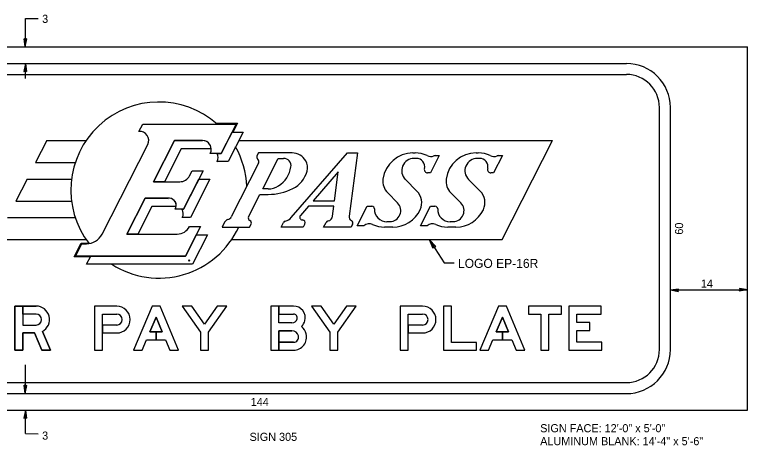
# Model space of a CAD drawing. Extents: x 60714 to 61340, y 9359 to 9750.
# Drawn here: x 60840.2 to 61093.4, y 9422.7 to 9571.4 of the extents above; entities that cross this region are included whole.
import ezdxf

# ---------------------------------------------------------------- set-up
doc = ezdxf.new("R2010")
doc.units = 0
for name, color, linetype in [('1', 7, 'Continuous'), ('2', 7, 'Continuous'), ('52', 7, 'Continuous'), ('GSBWFill', 7, 'Continuous'), ('SignPanel', 7, 'Continuous')]:
    doc.layers.add(name, color=color, linetype=linetype)

msp = doc.modelspace()

# ---------------------------------------------------------------- linework, layer by layer
at = {"layer": '1'}
for p, q in [((60843.93, 9570.16), (60848.33, 9570.13)), ((60843.93, 9560.27), (60843.93, 9570.16)), ((60843.93, 9549.38), (60843.93, 9554.57)), ((60983.43, 9493.77), (60988.67, 9485.78)), ((60988.67, 9485.78), (60992.11, 9485.78)), ((61066.77, 9476.35), (61093.37, 9476.35)), ((60843.93, 9440.57), (60843.93, 9450.46)), ((60843.93, 9426.76), (60843.93, 9434.87)), ((60843.93, 9426.76), (60848.33, 9426.73))]:
    msp.add_line(p, q, dxfattribs=at)
msp.add_circle((60900.51, 9486.52), 0.19, dxfattribs=at)
at = {"layer": '2'}
for p, q in [((60766.57, 9560.27), (61093.37, 9560.27)), ((61093.37, 9434.87), (61093.37, 9560.27)), ((60766.57, 9434.87), (61093.37, 9434.87))]:
    msp.add_line(p, q, dxfattribs=at)
at = {"layer": '52'}
for p, q in [((60843.91, 9560.35), (60843.47, 9563.13)), ((60843.96, 9562.91), (60843.47, 9563.13)), ((60843.91, 9560.35), (60843.73, 9563.01)), ((60843.91, 9560.35), (60844.45, 9563.11)), ((60843.91, 9560.35), (60844.19, 9563)), ((60844.45, 9563.11), (60843.96, 9562.91)), ((60843.93, 9554.57), (60843.39, 9551.81)), ((60843.93, 9554.57), (60843.65, 9551.92)), ((60843.93, 9554.57), (60844.37, 9551.8)), ((60843.93, 9554.57), (60844.11, 9551.91)), ((60843.39, 9551.81), (60843.88, 9552.02)), ((60843.88, 9552.02), (60844.37, 9551.8)), ((60983.43, 9493.77), (60984.68, 9490.74)), ((60985.7, 9491.41), (60983.43, 9493.77)), ((60984.68, 9490.74), (60985.06, 9491.28)), ((60985.06, 9491.28), (60985.7, 9491.41)), ((61066.77, 9476.35), (61069.55, 9476.8)), ((61066.77, 9476.35), (61069.43, 9476.54)), ((61066.77, 9476.35), (61069.53, 9475.82)), ((61066.77, 9476.35), (61069.42, 9476.08)), ((61069.33, 9476.31), (61069.55, 9476.8)), ((61069.53, 9475.82), (61069.33, 9476.31)), ((61090.81, 9476.4), (61090.59, 9475.91)), ((61093.37, 9476.35), (61090.59, 9475.91)), ((61093.37, 9476.35), (61090.61, 9476.89)), ((61090.61, 9476.89), (61090.81, 9476.4)), ((61093.37, 9476.35), (61090.71, 9476.63)), ((61093.37, 9476.35), (61090.71, 9476.17)), ((60843.91, 9440.65), (60843.47, 9443.43)), ((60843.96, 9443.21), (60843.47, 9443.43)), ((60843.91, 9440.65), (60843.73, 9443.31)), ((60843.91, 9440.65), (60844.45, 9443.41)), ((60843.91, 9440.65), (60844.19, 9443.3)), ((60844.45, 9443.41), (60843.96, 9443.21)), ((60843.93, 9434.87), (60843.39, 9432.11)), ((60843.93, 9434.87), (60843.65, 9432.22)), ((60843.93, 9434.87), (60844.37, 9432.1)), ((60843.93, 9434.87), (60844.11, 9432.21)), ((60843.39, 9432.11), (60843.88, 9432.32)), ((60843.88, 9432.32), (60844.37, 9432.1))]:
    msp.add_line(p, q, dxfattribs=at)
at = {"layer": 'GSBWFill'}
for p, q in [((60870.55, 9468.04), (60875.49, 9468.04)), ((60870.55, 9468.04), (60875.49, 9468.04)), ((60870.55, 9468.04), (60875.49, 9468.04)), ((60976.21, 9468.04), (60981.15, 9468.04)), ((60976.21, 9468.04), (60981.15, 9468.04)), ((60976.21, 9468.04), (60981.15, 9468.04)), ((60870.55, 9461.5), (60875.49, 9461.5)), ((60976.21, 9461.5), (60981.15, 9461.5)), ((60928.78, 9455.57), (60936.6, 9455.57))]:
    msp.add_line(p, q, dxfattribs=at)
for points in [[(60847.64, 9470.77), (60840.29, 9470.77), (60840.29, 9455.57), (60843.03, 9455.57), (60843.03, 9461.5), (60847.06, 9461.5), (60849.62, 9455.57), (60852.61, 9455.57), (60849.81, 9462.04)], [(60849.81, 9462.04), (60852.61, 9455.57), (60849.62, 9455.57), (60847.06, 9461.5), (60843.03, 9461.5), (60843.03, 9455.57), (60840.29, 9455.57), (60840.29, 9470.77), (60843.03, 9470.77), (60843.03, 9464.24), (60847.64, 9464.24)], [(60849.81, 9462.04), (60852.61, 9455.57), (60849.62, 9455.57), (60847.06, 9461.5), (60843.03, 9461.5), (60843.03, 9455.57), (60840.29, 9455.57), (60840.29, 9470.77), (60843.03, 9470.77), (60843.03, 9464.24), (60847.64, 9464.24)], [(60843.03, 9468.04), (60843.03, 9470.77), (60847.64, 9470.77)], [(60843.03, 9468.04), (60843.03, 9470.77), (60847.64, 9470.77)], [(60875.49, 9470.77), (60867.81, 9470.77), (60867.81, 9455.57), (60870.55, 9455.57), (60870.55, 9461.5)], [(60875.49, 9470.77), (60867.81, 9470.77), (60867.81, 9455.57), (60870.55, 9455.57), (60870.55, 9468.04)], [(60875.49, 9470.77), (60867.81, 9470.77), (60867.81, 9455.57), (60870.55, 9455.57), (60870.55, 9468.04)], [(60936.6, 9470.77), (60928.78, 9470.77), (60928.78, 9455.57)], [(60936.02, 9465), (60931.51, 9465), (60931.51, 9470.77), (60928.78, 9470.77), (60928.78, 9455.57), (60931.51, 9455.57)], [(60936.02, 9465), (60931.51, 9465), (60931.51, 9470.77), (60928.78, 9470.77), (60928.78, 9455.57), (60931.51, 9455.57)], [(60936.6, 9470.77), (60931.51, 9470.77), (60931.51, 9468.04), (60936.6, 9468.04)], [(60936.6, 9470.77), (60931.51, 9470.77), (60931.51, 9468.04), (60936.6, 9468.04)], [(60981.15, 9470.77), (60973.47, 9470.77), (60973.47, 9455.57), (60976.21, 9455.57), (60976.21, 9461.5)], [(60981.15, 9470.77), (60973.47, 9470.77), (60973.47, 9455.57), (60976.21, 9455.57), (60976.21, 9468.04)], [(60981.15, 9470.77), (60973.47, 9470.77), (60973.47, 9455.57), (60976.21, 9455.57), (60976.21, 9468.04)], [(60847.64, 9468.04), (60843.03, 9468.04), (60843.03, 9464.24), (60847.64, 9464.24)], [(60847.64, 9468.04), (60843.03, 9468.04)], [(60847.64, 9468.04), (60843.03, 9468.04)], [(60875.49, 9464.24), (60870.55, 9464.24), (60870.55, 9468.04)], [(60936.02, 9465), (60931.51, 9465), (60931.51, 9468.04), (60936.6, 9468.04)], [(60981.15, 9464.24), (60976.21, 9464.24), (60976.21, 9468.04)], [(60875.49, 9464.24), (60870.55, 9464.24), (60870.55, 9461.5), (60875.49, 9461.5)], [(60875.49, 9464.24), (60870.55, 9464.24), (60870.55, 9461.5), (60875.49, 9461.5)], [(60936.02, 9462.26), (60931.51, 9462.26), (60931.51, 9458.31), (60936.6, 9458.31)], [(60931.51, 9455.57), (60931.51, 9462.26), (60936.02, 9462.26)], [(60931.51, 9455.57), (60931.51, 9462.26), (60936.02, 9462.26)], [(60981.15, 9464.24), (60976.21, 9464.24), (60976.21, 9461.5), (60981.15, 9461.5)], [(60981.15, 9464.24), (60976.21, 9464.24), (60976.21, 9461.5), (60981.15, 9461.5)], [(60936.6, 9458.31), (60931.51, 9458.31), (60931.51, 9455.57), (60936.6, 9455.57)], [(60936.6, 9458.31), (60931.51, 9458.31), (60931.51, 9455.57), (60936.6, 9455.57)]]:
    msp.add_lwpolyline(points, dxfattribs=at)
for points in [[(60885.81, 9459.14), (60892.38, 9459.14), (60893.88, 9455.57), (60896.85, 9455.57), (60890.46, 9470.77), (60887.73, 9470.77), (60881.34, 9455.57), (60884.31, 9455.57)], [(60891.23, 9461.88), (60889.09, 9461.88), (60889.09, 9459.14), (60892.38, 9459.14), (60893.88, 9455.57), (60896.85, 9455.57), (60890.46, 9470.77), (60887.73, 9470.77), (60881.34, 9455.57), (60884.31, 9455.57), (60885.81, 9459.14), (60889.09, 9459.14), (60889.09, 9461.88), (60886.96, 9461.88), (60889.09, 9466.96)], [(60891.23, 9461.88), (60889.09, 9461.88), (60889.09, 9459.14), (60892.38, 9459.14), (60893.88, 9455.57), (60896.85, 9455.57), (60890.46, 9470.77), (60887.73, 9470.77), (60881.34, 9455.57), (60884.31, 9455.57), (60885.81, 9459.14), (60889.09, 9459.14), (60889.09, 9461.88), (60886.96, 9461.88), (60889.09, 9466.96)], [(60907.19, 9461.73), (60913.57, 9470.77), (60910.22, 9470.77), (60905.82, 9464.54), (60901.41, 9470.77), (60898.06, 9470.77), (60904.45, 9461.73), (60904.45, 9455.57), (60907.19, 9455.57)], [(60907.19, 9461.73), (60913.57, 9470.77), (60910.22, 9470.77), (60905.82, 9464.54), (60901.41, 9470.77), (60898.06, 9470.77), (60904.45, 9461.73), (60904.45, 9455.57), (60907.19, 9455.57)], [(60907.19, 9461.73), (60913.57, 9470.77), (60910.22, 9470.77), (60905.82, 9464.54), (60901.41, 9470.77), (60898.06, 9470.77), (60904.45, 9461.73), (60904.45, 9455.57), (60907.19, 9455.57)], [(60951.88, 9461.73), (60958.27, 9470.77), (60954.92, 9470.77), (60950.52, 9464.54), (60946.11, 9470.77), (60942.76, 9470.77), (60949.15, 9461.73), (60949.15, 9455.57), (60951.88, 9455.57)], [(60951.88, 9461.73), (60958.27, 9470.77), (60954.92, 9470.77), (60950.52, 9464.54), (60946.11, 9470.77), (60942.76, 9470.77), (60949.15, 9461.73), (60949.15, 9455.57), (60951.88, 9455.57)], [(60951.88, 9461.73), (60958.27, 9470.77), (60954.92, 9470.77), (60950.52, 9464.54), (60946.11, 9470.77), (60942.76, 9470.77), (60949.15, 9461.73), (60949.15, 9455.57), (60951.88, 9455.57)], [(60999.78, 9455.57), (60999.78, 9458.23), (60991.11, 9458.23), (60991.11, 9470.77), (60988.37, 9470.77), (60988.37, 9455.57)], [(60999.78, 9455.57), (60999.78, 9458.23), (60991.11, 9458.23), (60991.11, 9470.77), (60988.37, 9470.77), (60988.37, 9455.57)], [(60999.78, 9455.57), (60999.78, 9458.23), (60991.11, 9458.23), (60991.11, 9470.77), (60988.37, 9470.77), (60988.37, 9455.57)], [(61005.46, 9459.14), (61012.03, 9459.14), (61013.53, 9455.57), (61016.5, 9455.57), (61010.11, 9470.77), (61007.38, 9470.77), (61000.99, 9455.57), (61003.96, 9455.57)], [(61010.88, 9461.88), (61008.75, 9461.88), (61008.75, 9459.14), (61012.03, 9459.14), (61013.53, 9455.57), (61016.5, 9455.57), (61010.11, 9470.77), (61007.38, 9470.77), (61000.99, 9455.57), (61003.96, 9455.57), (61005.46, 9459.14), (61008.75, 9459.14), (61008.75, 9461.88), (61006.61, 9461.88), (61008.75, 9466.96)], [(61010.88, 9461.88), (61008.75, 9461.88), (61008.75, 9459.14), (61012.03, 9459.14), (61013.53, 9455.57), (61016.5, 9455.57), (61010.11, 9470.77), (61007.38, 9470.77), (61000.99, 9455.57), (61003.96, 9455.57), (61005.46, 9459.14), (61008.75, 9459.14), (61008.75, 9461.88), (61006.61, 9461.88), (61008.75, 9466.96)], [(61017.72, 9468.04), (61022.05, 9468.04), (61022.05, 9455.57), (61024.79, 9455.57), (61024.79, 9468.04), (61029.12, 9468.04), (61029.12, 9470.77), (61017.72, 9470.77)], [(61017.72, 9468.04), (61022.05, 9468.04), (61022.05, 9455.57), (61024.79, 9455.57), (61024.79, 9468.04), (61029.12, 9468.04), (61029.12, 9470.77), (61017.72, 9470.77)], [(61017.72, 9468.04), (61022.05, 9468.04), (61022.05, 9455.57), (61024.79, 9455.57), (61024.79, 9468.04), (61029.12, 9468.04), (61029.12, 9470.77), (61017.72, 9470.77)], [(61043.11, 9458.31), (61034.44, 9458.31), (61034.44, 9462.4), (61038.92, 9462.4), (61038.92, 9465.13), (61034.44, 9465.13), (61034.44, 9468.04), (61042.88, 9468.04), (61042.88, 9470.77), (61031.7, 9470.77), (61031.7, 9455.57), (61043.11, 9455.57)], [(61043.11, 9458.31), (61034.44, 9458.31), (61034.44, 9462.4), (61038.92, 9462.4), (61038.92, 9465.13), (61034.44, 9465.13), (61034.44, 9468.04), (61042.88, 9468.04), (61042.88, 9470.77), (61031.7, 9470.77), (61031.7, 9455.57), (61043.11, 9455.57)], [(61043.11, 9458.31), (61034.44, 9458.31), (61034.44, 9462.4), (61038.92, 9462.4), (61038.92, 9465.13), (61034.44, 9465.13), (61034.44, 9468.04), (61042.88, 9468.04), (61042.88, 9470.77), (61031.7, 9470.77), (61031.7, 9455.57), (61043.11, 9455.57)], [(60891.23, 9461.88), (60889.09, 9466.96), (60886.96, 9461.88)], [(61010.88, 9461.88), (61008.75, 9466.96), (61006.61, 9461.88)]]:
    msp.add_lwpolyline(points, close=True, dxfattribs=at)
for centre, radius, start, end in [((60847.64, 9466.14), 4.64, 297.837, 90), ((60847.64, 9466.14), 4.64, 297.837, 90), ((60847.64, 9466.14), 4.64, 297.837, 90), ((60936.6, 9466.75), 4.03, 345.5225, 90), ((60936.6, 9466.75), 4.03, 345.5225, 90), ((60936.6, 9466.75), 4.03, 345.5225, 90), ((60847.64, 9466.14), 1.9, 270, 90), ((60847.64, 9466.14), 1.9, 270, 90), ((60847.64, 9466.14), 1.9, 270, 90), ((60936.6, 9466.75), 1.29, 345.5225, 90), ((60936.6, 9466.75), 1.29, 345.5225, 90), ((60936.6, 9466.75), 1.29, 345.5225, 90), ((60936.02, 9466.9), 1.9, 270, 345.5225), ((60936.02, 9466.9), 1.9, 270, 345.5225), ((60936.02, 9466.9), 1.9, 270, 345.5225), ((60936.02, 9466.9), 4.64, 316.7114, 345.5225), ((60936.02, 9466.9), 4.64, 316.7114, 345.5225), ((60936.02, 9466.9), 4.64, 316.7114, 345.5225), ((60936.02, 9459.9), 2.36, 14.4775, 90), ((60936.02, 9459.9), 2.36, 14.4775, 90), ((60936.02, 9459.9), 2.36, 14.4775, 90), ((60936.02, 9459.9), 5.09, 14.4775, 48.4921), ((60936.02, 9459.9), 5.09, 14.4775, 48.4921), ((60936.02, 9459.9), 5.09, 14.4775, 48.4921), ((60936.6, 9460.06), 4.49, 270, 14.4775), ((60936.6, 9460.06), 4.49, 270, 14.4775), ((60936.6, 9460.06), 4.49, 270, 14.4775), ((60936.6, 9460.06), 1.75, 270, 14.4775), ((60936.6, 9460.06), 1.75, 270, 14.4775), ((60936.6, 9460.06), 1.75, 270, 14.4775)]:
    msp.add_arc(centre, radius, start, end, dxfattribs=at)
for centre, major_axis in [((60875.49, 9466.14), (0, 4.64)), ((60875.49, 9466.14), (0, 4.64)), ((60875.49, 9466.14), (0, 4.64)), ((60981.15, 9466.14), (0, 4.64)), ((60981.15, 9466.14), (0, 4.64)), ((60981.15, 9466.14), (0, 4.64)), ((60875.49, 9466.14), (0, 1.9)), ((60875.49, 9466.14), (0, 1.9)), ((60875.49, 9466.14), (0, 1.9)), ((60981.15, 9466.14), (0, 1.9)), ((60981.15, 9466.14), (0, 1.9)), ((60981.15, 9466.14), (0, 1.9))]:
    msp.add_ellipse(centre, major_axis=major_axis, ratio=0.999994, start_param=3.141593, end_param=6.283185, dxfattribs=at)
at = {"layer": 'SignPanel'}
for p, q in [((60808.37, 9554.57), (61051.57, 9554.57)), ((60808.37, 9550.77), (61051.57, 9550.77)), ((61062.97, 9455.77), (61062.97, 9539.37)), ((61066.77, 9455.77), (61066.77, 9539.37)), ((60883.19, 9531.13), (60884.49, 9533.67)), ((60884.49, 9533.67), (60916.79, 9533.67)), ((60909.85, 9533.96), (60917.25, 9533.96)), ((60916.79, 9533.67), (60911.62, 9523.52)), ((60917.25, 9533.96), (60915.66, 9530.83)), ((60911.61, 9523.51), (60915.34, 9530.83)), ((60911.61, 9523.51), (60915.34, 9530.83)), ((60919.18, 9530.83), (60914, 9520.67)), ((60919.18, 9530.83), (60914, 9520.67)), ((60915.34, 9530.83), (60919.18, 9530.83)), ((60915.34, 9530.83), (60919.18, 9530.83)), ((60851.31, 9527.97), (60847.44, 9520.37)), ((60851.31, 9527.97), (60864.93, 9527.97)), ((60870.43, 9495.63), (60886.2, 9526.58)), ((60895.44, 9527.97), (60888.18, 9513.73)), ((60888.18, 9513.73), (60895.44, 9527.97)), ((60888.18, 9513.73), (60895.44, 9527.97)), ((60905.12, 9527.97), (60895.44, 9527.97)), ((60895.44, 9527.97), (60905.12, 9527.97)), ((60895.44, 9527.97), (60905.12, 9527.97)), ((60917.72, 9527.97), (61026.11, 9527.97)), ((61008.68, 9493.77), (61026.11, 9527.97)), ((60897.82, 9525.13), (60892.01, 9513.73)), ((60897.82, 9525.13), (60892.01, 9513.73)), ((60908.16, 9525.13), (60897.82, 9525.13)), ((60908.16, 9525.13), (60897.82, 9525.13)), ((60911.62, 9523.52), (60907.81, 9523.52)), ((60910.2, 9523.51), (60911.61, 9523.51)), ((60910.2, 9523.51), (60911.61, 9523.51)), ((60924.46, 9523.7), (60923.94, 9522.69)), ((60936.09, 9523.7), (60924.46, 9523.7)), ((60935.8, 9501.39), (60955.21, 9523.7)), ((60955.21, 9523.7), (60958.63, 9523.7)), ((60958.63, 9523.7), (60955.78, 9501.83)), ((60977.84, 9523.7), (60978.56, 9523.7)), ((60999.7, 9523.7), (61000.42, 9523.7)), ((60914, 9520.67), (60910.2, 9520.67)), ((60914, 9520.67), (60910.2, 9520.67)), ((60925.95, 9511.25), (60931.33, 9521.8)), ((60931.33, 9521.8), (60933.16, 9521.8)), ((60979.05, 9521.8), (60978.23, 9521.8)), ((60986.88, 9522.75), (60983.86, 9516.82)), ((60985.46, 9522.75), (60986.88, 9522.75)), ((61000.9, 9521.8), (61000.08, 9521.8)), ((61008.73, 9522.75), (61005.71, 9516.82)), ((61007.31, 9522.75), (61008.73, 9522.75)), ((60847.44, 9520.37), (60861.19, 9520.37)), ((60924.49, 9520.11), (60915.08, 9501.65)), ((60905.33, 9517.53), (60898.56, 9504.23)), ((60900.65, 9515.8), (60901.53, 9517.53)), ((60901.53, 9517.53), (60905.33, 9517.53)), ((60952.02, 9517.15), (60943.35, 9507.17)), ((60950.73, 9507.17), (60952.02, 9517.15)), ((60983.86, 9516.82), (60982.91, 9516.82)), ((61005.71, 9516.82), (61004.76, 9516.82)), ((60844.54, 9514.67), (60840.67, 9507.07)), ((60844.54, 9514.67), (60859.91, 9514.67)), ((60888.18, 9513.73), (60897.27, 9513.73)), ((60892.01, 9513.73), (60888.18, 9513.73)), ((60892.01, 9513.73), (60888.18, 9513.73)), ((60898.56, 9504.23), (60903.88, 9514.67)), ((60898.56, 9504.23), (60903.88, 9514.67)), ((60907.72, 9514.67), (60900.94, 9501.37)), ((60907.72, 9514.67), (60900.94, 9501.37)), ((60903.88, 9514.67), (60907.72, 9514.67)), ((60903.88, 9514.67), (60907.72, 9514.67)), ((60975.21, 9514.5), (60979.19, 9510.52)), ((60997.06, 9514.5), (61001.04, 9510.52)), ((60927.83, 9511.25), (60925.95, 9511.25)), ((60885.27, 9508.03), (60878.98, 9495.67)), ((60878.98, 9495.67), (60885.27, 9508.03)), ((60878.98, 9495.67), (60885.27, 9508.03)), ((60893.61, 9508.03), (60885.27, 9508.03)), ((60885.27, 9508.03), (60893.25, 9508)), ((60885.27, 9508.03), (60893.25, 9508)), ((60921.05, 9501.65), (60924.98, 9509.35)), ((60924.98, 9509.35), (60927.83, 9509.35)), ((60972.52, 9506.44), (60969.11, 9509.85)), ((60994.38, 9506.44), (60990.96, 9509.85)), ((60840.67, 9507.07), (60859.91, 9507.07)), ((60941.7, 9505.27), (60938.95, 9502.1)), ((60950.53, 9505.27), (60941.7, 9505.27)), ((60943.35, 9507.17), (60950.73, 9507.17)), ((60950.08, 9501.83), (60950.53, 9505.27)), ((60958.61, 9498.53), (60962.06, 9505.3)), ((60962.06, 9505.3), (60963.59, 9505.3)), ((60980.46, 9498.53), (60983.91, 9505.3)), ((60983.91, 9505.3), (60985.44, 9505.3)), ((60887.66, 9505.17), (60882.82, 9495.67)), ((60887.66, 9505.17), (60882.82, 9495.67)), ((60896.05, 9505.14), (60887.66, 9505.17)), ((60896.05, 9505.14), (60887.66, 9505.17)), ((60898.56, 9504.23), (60895.69, 9504.23)), ((60897.96, 9504.23), (60898.56, 9504.23)), ((60897.96, 9504.23), (60898.56, 9504.23)), ((60837.77, 9501.37), (60861.19, 9501.37)), ((60900.94, 9501.37), (60898.09, 9501.37)), ((60900.94, 9501.37), (60898.09, 9501.37)), ((60904.43, 9498.23), (60899.26, 9488.07)), ((60900.63, 9498.23), (60904.43, 9498.23)), ((60912.77, 9499.73), (60911.92, 9498.05)), ((60911.92, 9498.05), (60921.42, 9498.05)), ((60921.42, 9498.05), (60921.94, 9499.07)), ((60932.31, 9498.05), (60933.13, 9499.67)), ((60939.91, 9498.05), (60932.31, 9498.05)), ((60940.47, 9499.15), (60939.91, 9498.05)), ((60946.97, 9498.05), (60947.81, 9499.7)), ((60956.47, 9498.05), (60946.97, 9498.05)), ((60956.97, 9499.03), (60956.47, 9498.05)), ((60960.92, 9498.53), (60958.61, 9498.53)), ((60970.86, 9498.05), (60968, 9498.05)), ((60968.81, 9499.95), (60969.84, 9499.95)), ((60982.77, 9498.53), (60980.46, 9498.53)), ((60992.71, 9498.05), (60989.85, 9498.05)), ((60990.66, 9499.95), (60991.69, 9499.95)), ((60878.98, 9495.67), (60896.42, 9495.67)), ((60882.82, 9495.67), (60878.98, 9495.67)), ((60882.82, 9495.67), (60878.98, 9495.67)), ((60899.26, 9488.07), (60902.98, 9495.38)), ((60899.26, 9488.07), (60902.98, 9495.38)), ((60906.82, 9495.38), (60901.64, 9485.23)), ((60906.82, 9495.38), (60901.64, 9485.23)), ((60902.98, 9495.38), (60906.82, 9495.38)), ((60902.98, 9495.38), (60906.82, 9495.38)), ((60833.9, 9493.77), (60864.93, 9493.77)), ((60915.2, 9493.77), (61008.68, 9493.77)), ((60860.85, 9487.83), (60863.26, 9492.55)), ((60861.26, 9488.07), (60863.41, 9492.31)), ((60863.26, 9492.55), (60865.01, 9492.55)), ((60863.41, 9492.31), (60865.01, 9492.31)), ((60866.38, 9487.83), (60860.85, 9487.83)), ((60899.26, 9488.07), (60861.26, 9488.07)), ((60865.06, 9485.23), (60866.51, 9488.07)), ((60865.06, 9485.23), (60866.51, 9488.07)), ((60866.51, 9488.07), (60899.26, 9488.07)), ((60866.51, 9488.07), (60899.26, 9488.07)), ((60901.64, 9485.23), (60865.06, 9485.23)), ((60901.64, 9485.23), (60865.06, 9485.23)), ((60808.37, 9444.37), (61051.57, 9444.37)), ((60808.37, 9440.57), (61051.57, 9440.57))]:
    msp.add_line(p, q, dxfattribs=at)
for centre, radius, start, end in [((61051.57, 9539.37), 15.2, 0, 90), ((61051.57, 9539.37), 11.4, 0, 90), ((60890.07, 9510.87), 30.4, 48.5904, 217.4727), ((60883.4, 9528), 3.14, 332.9998, 93.8045), ((60905.12, 9524.93), 3.04, 332.2089, 90), ((60905.12, 9524.93), 3.04, 3.5833, 90), ((60905.12, 9524.93), 3.04, 3.5833, 90), ((60890.07, 9510.87), 30.4, 2.4236, 29.2771), ((60907.51, 9522.08), 3.04, 332.2089, 27.9127), ((60907.51, 9522.08), 3.04, 332.2089, 27.9127), ((60936.09, 9518.28), 5.42, 29.4315, 90), ((60977.84, 9513.25), 10.45, 90, 172.3089), ((60978.56, 9514.2), 9.5, 64.0896, 90), ((60999.69, 9513.25), 10.45, 90, 172.3089), ((61000.41, 9514.2), 9.5, 64.0896, 90), ((60924.79, 9522.25), 0.95, 152.9784, 231.1602), ((60923.48, 9520.62), 1.14, 333.0027, 51.1602), ((60933.15, 9519.23), 2.57, 351.076, 90), ((60936.67, 9518.61), 4.75, 344.7074, 29.4315), ((60978.23, 9517.52), 4.28, 90, 225), ((60979.05, 9518.95), 2.85, 345.6915, 90), ((60983.96, 9525.31), 2.85, 244.0896, 292.0347), ((60985.46, 9521.61), 1.14, 90, 112.0347), ((61000.08, 9517.52), 4.28, 90, 225), ((61000.9, 9518.95), 2.85, 345.6915, 90), ((61005.81, 9525.31), 2.85, 244.0896, 292.0347), ((61007.31, 9521.61), 1.14, 90, 112.0347), ((60926.3, 9520.31), 9.5, 302.4206, 351.076), ((60982.91, 9517.96), 1.14, 165.6915, 270), ((61004.76, 9517.96), 1.14, 165.6915, 270), ((60897.27, 9517.52), 3.8, 270, 332.9883), ((60932.09, 9519.86), 9.5, 296.6432, 344.7074), ((60973.14, 9513.88), 5.7, 172.3089, 225), ((60994.99, 9513.88), 5.7, 172.3089, 225), ((60927.83, 9517.9), 6.65, 270, 302.4206), ((60927.83, 9528.35), 19, 270, 296.6432), ((60975.16, 9506.49), 5.7, 334.95, 45), ((60997.01, 9506.49), 5.7, 334.95, 45), ((60893.61, 9505.55), 2.47, 350.3502, 98.3344), ((60893.61, 9505.55), 2.47, 350.3502, 98.3344), ((60893.61, 9505.55), 2.47, 327.421, 90), ((60963.59, 9504.34), 0.95, 358.6665, 90), ((60969.84, 9503.75), 3.8, 270, 45), ((60985.44, 9504.34), 0.95, 358.6665, 90), ((60991.69, 9503.75), 3.8, 270, 45), ((60896.01, 9502.7), 2.47, 327.421, 37.9799), ((60896.01, 9502.7), 2.47, 327.421, 37.9799), ((60968.81, 9504.22), 4.28, 178.6665, 270), ((60970.86, 9508.5), 10.45, 270, 334.95), ((60990.66, 9504.22), 4.28, 178.6665, 270), ((60992.71, 9508.5), 10.45, 270, 334.95), ((60914.47, 9498.86), 1.9, 106.4317, 152.9742), ((60913.39, 9502.5), 1.9, 286.4317, 332.9959), ((60921.9, 9501.21), 0.95, 152.9884, 244.7832), ((60921.09, 9499.49), 0.95, 333.0239, 64.7832), ((60933.98, 9499.24), 0.95, 102.7162, 153.0239), ((60932.94, 9503.87), 3.8, 282.7162, 318.9966), ((60939.67, 9501.48), 0.95, 138.9824, 268.6869), ((60939.62, 9499.58), 0.95, 332.9784, 88.6869), ((60948.66, 9499.26), 0.95, 99.2397, 153.0239), ((60948.2, 9502.08), 1.9, 279.2397, 352.5632), ((60957.29, 9501.64), 1.52, 172.5884, 241.8673), ((60956.12, 9499.46), 0.95, 332.9784, 61.8673), ((60890.07, 9510.87), 30.4, 237.5383, 335.047), ((60896.42, 9500.42), 4.75, 270, 332.5096), ((60962.74, 9496.58), 2.66, 64.3795, 133.1892), ((60968, 9507.55), 9.5, 244.3795, 270), ((60984.59, 9496.58), 2.66, 64.3795, 133.1892), ((60989.85, 9507.55), 9.5, 244.3795, 270), ((60865.01, 9498.38), 6.08, 270, 332.9991), ((60865.01, 9498.38), 5.83, 270, 277.5038), ((61051.57, 9455.77), 15.2, 270, 0), ((61051.57, 9455.77), 11.4, 270, 0)]:
    msp.add_arc(centre, radius, start, end, dxfattribs=at)

# ---------------------------------------------------------------- texts
at = {"layer": '1'}
for s, height, rotation, p in [('3', 2.8, 0, (60849.73, 9568.59)), ('60', 2.8, 90, (61071.18, 9495.46)), ('LOGO EP-16R', 3.1111, 0, (60993.4, 9483.98)), ('14', 2.8, 0, (61077.31, 9477.14)), ('144', 2.8, 0, (60921.79, 9436.3)), ('3', 2.8, 0, (60849.73, 9424.67)), ('SIGN 305', 2.8, 0, (60921.39, 9424.24))]:
    msp.add_text(s, height=height, rotation=rotation, dxfattribs=at).set_placement(p)
at = {"layer": '2'}
for s, p in [('SIGN FACE: 12\'-0" x 5\'-0"', (61021.8, 9427.22)), ('ALUMINUM BLANK: 14\'-4" x 5\'-6"', (61021.8, 9422.74))]:
    msp.add_text(s, height=2.8, rotation=0, dxfattribs=at).set_placement(p)

doc.saveas('drawing.dxf')
